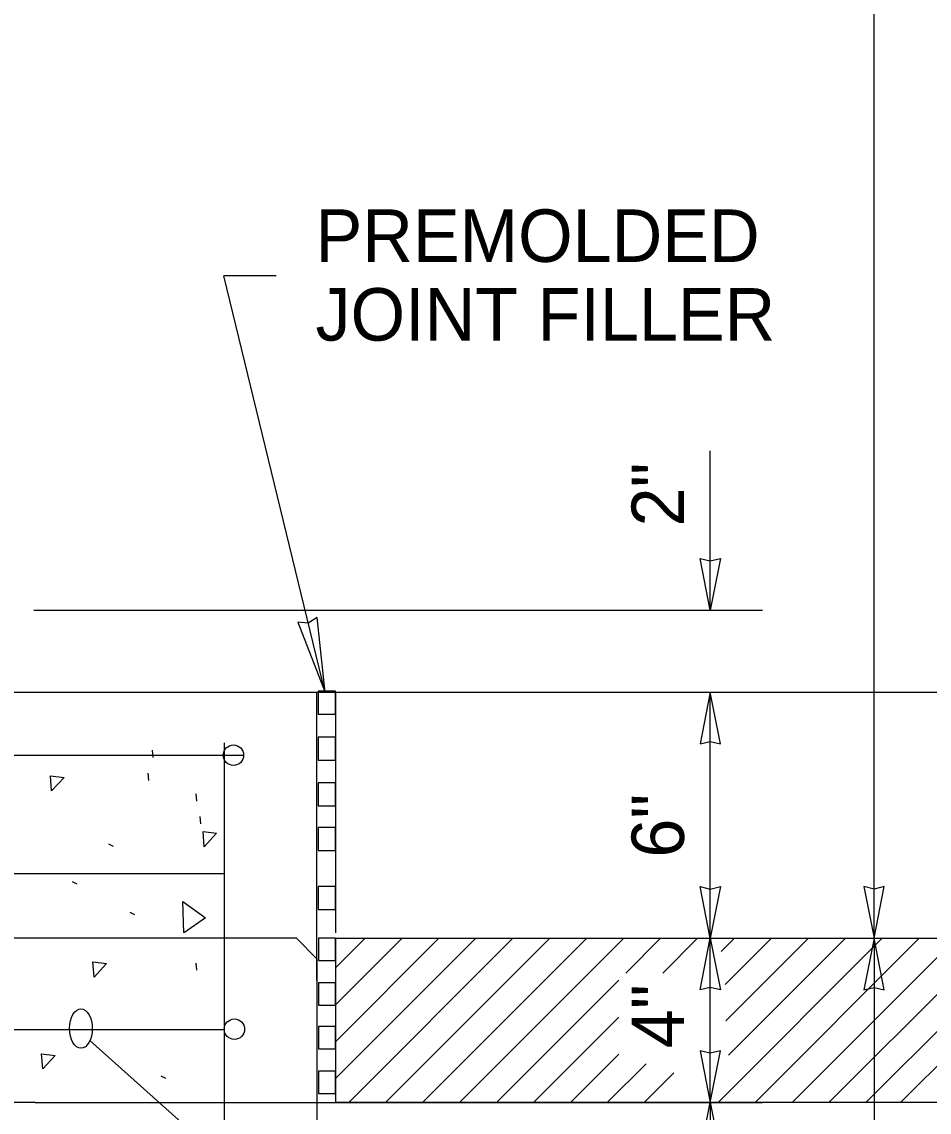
# Model space of a CAD drawing. Extents: x 99862 to 103680, y 99470 to 105076.
# Drawn here: x 101474.1 to 101751, y 103641.6 to 103974.1 of the extents above; entities that cross this region are included whole.
import ezdxf

# ---------------------------------------------------------------- set-up
doc = ezdxf.new("R2010")
doc.units = 0
for name, color, linetype in [('Level 1', 7, 'Continuous'), ('Level 10', 7, 'Continuous'), ('Level 11', 7, 'Continuous'), ('Level 15', 7, 'Continuous'), ('Level 18', 7, 'Continuous'), ('Level 19', 7, 'Continuous'), ('Level 20', 7, 'Continuous'), ('Level 25', 7, 'Continuous'), ('Level 7', 7, 'Continuous'), ('Level 8', 7, 'Continuous')]:
    doc.layers.add(name, color=color, linetype=linetype)

msp = doc.modelspace()

# ---------------------------------------------------------------- linework, layer by layer
at = {"layer": 'Level 1'}
for p, q in [((101264.13, 103769.65), (101564.13, 103769.65)), ((101557.88, 103694.63), (101270.38, 103694.63)), ((101557.88, 103694.63), (101564.13, 103688.38)), ((101564.13, 103688.38), (101564.17, 103232.26))]:
    msp.add_line(p, q, dxfattribs=at)
at = {"layer": 'Level 10'}
msp.add_line((101564.13, 103681.78), (101564.13, 103769.65), dxfattribs=at)
for centre in [(101538.64, 103750.42), (101538.93, 103666.88)]:
    msp.add_circle(centre, 3.12, dxfattribs=at)
at = {"layer": 'Level 11'}
for p, q in [((101514.14, 103749.77), (101513.91, 103751.94)), ((101512.84, 103742.73), (101512.61, 103744.9)), ((101527.51, 103736.46), (101527.28, 103738.63)), ((101528.67, 103729.54), (101528.44, 103731.72)), ((101500.54, 103723.43), (101501.98, 103722.72)), ((101489.39, 103711.89), (101490.82, 103711.18)), ((101507.05, 103702.52), (101508.49, 103701.81)), ((101527.51, 103684.88), (101527.28, 103687.06)), ((101516.48, 103652.63), (101517.91, 103651.92))]:
    msp.add_line(p, q, dxfattribs=at)
for points in [[(101483.16, 103739.56), (101482.81, 103744.16), (101486.94, 103743.66), (101483.16, 103739.56)], [(101529.73, 103722.52), (101529.38, 103727.12), (101533.51, 103726.62), (101529.73, 103722.52)], [(101523.52, 103696.26), (101523.17, 103705.86), (101530.11, 103700.83), (101523.67, 103696.34)], [(101496.12, 103682.76), (101495.77, 103687.37), (101499.9, 103686.87), (101496.12, 103682.76)], [(101480.44, 103654.76), (101480.09, 103659.36), (101484.23, 103658.86), (101480.44, 103654.76)]]:
    msp.add_lwpolyline(points, dxfattribs=at)
at = {"layer": 'Level 15'}
for p, q in [((101734.13, 103694.63), (101734.13, 104359.78)), ((101551.69, 103896.58), (101535.69, 103896.58)), ((101566.65, 103769.55), (101535.69, 103896.58)), ((101684.13, 103794.65), (101684.13, 103843.21)), ((101477.72, 103794.65), (101700.13, 103794.65)), ((101574.13, 103769.65), (101700.13, 103769.65)), ((101684.13, 103694.63), (101684.13, 103769.65)), ((101684.13, 103644.56), (101684.13, 103694.63)), ((101734.13, 103694.63), (101734.17, 103232.26)), ((101582.9, 103584.75), (101494.85, 103663.38)), ((101478.16, 103644.56), (101700.13, 103644.56)), ((101684.13, 103644.56), (101684.17, 103385.18))]:
    msp.add_line(p, q, dxfattribs=at)
for points in [[(101684.13, 103794.65), (101681.05, 103810.38), (101684.13, 103809.65), (101687.22, 103810.38)], [(101566.65, 103769.55), (101564.14, 103792.44), (101561.49, 103790.7), (101558.34, 103791.02)], [(101684.13, 103769.65), (101681.05, 103753.93), (101684.13, 103754.65), (101687.22, 103753.93)], [(101684.13, 103694.63), (101681.05, 103710.35), (101684.13, 103709.62), (101687.22, 103710.35)], [(101734.13, 103694.63), (101737.22, 103710.35), (101734.13, 103709.62), (101731.05, 103710.35)], [(101684.13, 103694.63), (101687.22, 103678.9), (101684.13, 103679.63), (101681.05, 103678.9)], [(101734.13, 103694.63), (101731.05, 103678.9), (101734.13, 103679.63), (101737.22, 103678.9)], [(101684.13, 103644.56), (101687.22, 103660.28), (101684.13, 103659.55), (101681.05, 103660.28)], [(101684.13, 103644.56), (101687.22, 103628.83), (101684.13, 103629.56), (101681.05, 103628.83)]]:
    msp.add_lwpolyline(points, close=True, dxfattribs=at)
msp.add_ellipse((101492.11, 103667.07), major_axis=(0, 6), ratio=0.57735, dxfattribs=at)
at = {"layer": 'Level 18'}
for points in [[(101569.81, 103769.92), (101564.48, 103769.92), (101564.48, 103762.94), (101569.81, 103762.94)], [(101569.81, 103755.95), (101564.48, 103755.95), (101564.48, 103748.96), (101569.81, 103748.96)], [(101569.81, 103741.98), (101564.48, 103741.98), (101564.48, 103734.99), (101569.81, 103734.99)], [(101569.81, 103728.39), (101564.48, 103728.39), (101564.48, 103721.4), (101569.81, 103721.4)], [(101569.81, 103710.35), (101564.48, 103710.35), (101564.48, 103703.37), (101569.81, 103703.37)], [(101569.81, 103694.63), (101564.61, 103694.63), (101564.61, 103687.8), (101569.81, 103687.8)], [(101569.81, 103680.98), (101564.61, 103680.98), (101564.61, 103674.16), (101569.81, 103674.16)], [(101569.81, 103667.71), (101564.61, 103667.71), (101564.61, 103660.89), (101569.81, 103660.89)], [(101569.81, 103654.07), (101564.61, 103654.07), (101564.61, 103647.24), (101569.81, 103647.24)]]:
    msp.add_lwpolyline(points, close=True, dxfattribs=at)
at = {"layer": 'Level 19'}
for p, q in [((101569.78, 103685.6), (101578.81, 103694.63)), ((101569.81, 103651.81), (101612.63, 103694.63)), ((101569.87, 103674.41), (101590.08, 103694.63)), ((101569.89, 103663.16), (101601.36, 103694.63)), ((101573.91, 103644.63), (101623.91, 103694.63)), ((101585.19, 103644.63), (101635.18, 103694.63)), ((101596.46, 103644.63), (101646.46, 103694.63)), ((101607.73, 103644.63), (101657.73, 103694.63)), ((101658.39, 103684.01), (101669.01, 103694.63)), ((101669.66, 103684.01), (101680.28, 103694.63)), ((101686.66, 103644.63), (101736.65, 103694.63)), ((101687.5, 103690.57), (101691.56, 103694.63)), ((101688.73, 103680.53), (101702.83, 103694.63)), ((101688.92, 103669.45), (101714.1, 103694.63)), ((101689.74, 103658.99), (101725.38, 103694.63)), ((101697.93, 103644.63), (101747.93, 103694.63)), ((101709.21, 103644.63), (101759.2, 103694.63)), ((101720.48, 103644.63), (101770.48, 103694.63)), ((101731.75, 103644.63), (101781.75, 103694.63)), ((101742.32, 103644.63), (101792.32, 103694.63)), ((101619.01, 103644.63), (101656.22, 103681.84)), ((101630.28, 103644.63), (101656.22, 103670.56)), ((101641.56, 103644.63), (101656.22, 103659.29)), ((101652.83, 103644.63), (101664.55, 103656.35)), ((101664.11, 103644.63), (101673.06, 103653.58))]:
    msp.add_line(p, q, dxfattribs=at)
at = {"layer": 'Level 25'}
for p, q in [((101535.8, 103754.2), (101535.84, 103262.15)), ((101295.33, 103750.42), (101541.77, 103750.42)), ((101298.71, 103714.4), (101535.8, 103714.4)), ((101298.71, 103666.74), (101535.8, 103666.74))]:
    msp.add_line(p, q, dxfattribs=at)
at = {"layer": 'Level 7'}
for p, q in [((101564.13, 103769.65), (101827.91, 103769.65)), ((101569.81, 103769.65), (101569.81, 103696.23)), ((101569.81, 103694.63), (101569.82, 103644.63)), ((101570.02, 103694.63), (101827.57, 103694.63)), ((101569.82, 103644.63), (101827.97, 103644.63))]:
    msp.add_line(p, q, dxfattribs=at)
at = {"layer": 'Level 8'}
msp.add_line((101478.16, 103644.56), (101269.42, 103644.56), dxfattribs=at)

# ---------------------------------------------------------------- texts
at = {"layer": 'Level 20'}
for s, p in [('PREMOLDED ', (101563.69, 103900.85)), ('JOINT FILLER', (101563.69, 103876.85))]:
    msp.add_text(s, height=16, dxfattribs=at).set_placement(p)
for s, p in [('2"', (101676.13, 103820.18)), ('6"', (101676.13, 103719.18)), ('4"', (101676.13, 103661.1))]:
    msp.add_text(s, height=16, rotation=90, dxfattribs=at).set_placement(p)

doc.saveas('drawing.dxf')
